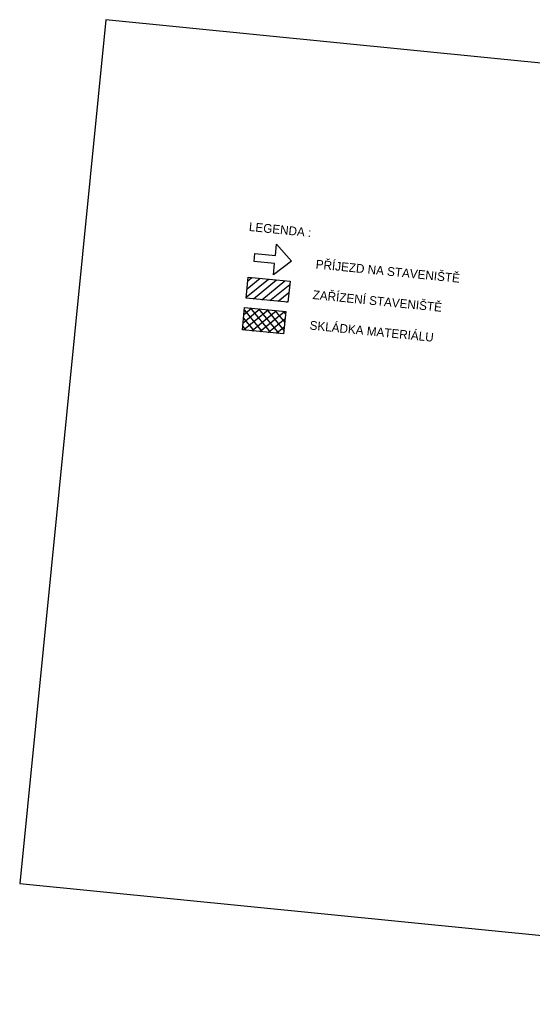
# Model space of a CAD drawing. Extents: x -517955 to -517507, y -1177194 to -1176857.
# Drawn here: x -517954.8 to -517779.6, y -1177194.3 to -1176857.1 of the extents above; entities that cross this region are included whole.
import ezdxf

# ---------------------------------------------------------------- set-up
doc = ezdxf.new("R2010")
doc.units = 0
doc.layers.add('označení lomového bodu', color=7, linetype='Continuous')

msp = doc.modelspace()

# ---------------------------------------------------------------- linework, layer by layer
at = {"layer": 'označení lomového bodu'}
for p, q in [((-517877.37, -1176952.06), (-517869.82, -1176945.88)), ((-517877.09, -1176949.25), (-517872.64, -1176945.6)), ((-517876.81, -1176946.43), (-517875.45, -1176945.32)), ((-517874.9, -1176952.63), (-517867.01, -1176946.16)), ((-517872.09, -1176952.91), (-517864.2, -1176946.44)), ((-517869.27, -1176953.19), (-517862.52, -1176947.66)), ((-517866.46, -1176953.47), (-517862.8, -1176950.47)), ((-517878.46, -1176960.79), (-517872.71, -1176956.08)), ((-517878.18, -1176957.97), (-517875.53, -1176955.8)), ((-517876.02, -1176955.75), (-517869.1, -1176964.19)), ((-517873.2, -1176956.03), (-517866.29, -1176964.47)), ((-517870.39, -1176956.31), (-517864.5, -1176963.5)), ((-517863.64, -1176953.75), (-517863.08, -1176953.29)), ((-517878.34, -1176963.27), (-517869.9, -1176956.36)), ((-517878.31, -1176959.26), (-517874.73, -1176963.63)), ((-517878.03, -1176956.45), (-517871.92, -1176963.91)), ((-517875.52, -1176963.55), (-517867.08, -1176956.64)), ((-517872.71, -1176963.83), (-517864.27, -1176956.92)), ((-517869.89, -1176964.11), (-517864.09, -1176959.36)), ((-517867.57, -1176956.59), (-517864.22, -1176960.68)), ((-517864.76, -1176956.87), (-517863.94, -1176957.87)), ((-517878.59, -1176962.08), (-517877.55, -1176963.35)), ((-517867.08, -1176964.39), (-517864.37, -1176962.18))]:
    msp.add_line(p, q, dxfattribs=at)
for points in [[(-517954.84, -1177152.67), (-517536.91, -1177194.29), (-517507.48, -1176898.75), (-517925.41, -1176857.13)], [(-517874.67, -1176939.8), (-517874.4, -1176937.1), (-517867.41, -1176937.8), (-517867.01, -1176933.88), (-517861.95, -1176939.7), (-517868.06, -1176944.41), (-517867.67, -1176940.49)], [(-517876.69, -1176945.2), (-517862.42, -1176946.62), (-517863.13, -1176953.8), (-517877.4, -1176952.38)], [(-517877.94, -1176955.56), (-517863.85, -1176956.96), (-517864.62, -1176964.64), (-517878.7, -1176963.24)]]:
    msp.add_lwpolyline(points, close=True, dxfattribs=at)

# ---------------------------------------------------------------- texts
for s, p in [('LEGENDA :', (-517876.58, -1176929.38)), ('PŘÍJEZD NA STAVENIŠTĚ', (-517853.74, -1176942.21)), ('ZAŘÍZENÍ STAVENIŠTĚ', (-517854.78, -1176952.66)), ('SKLÁDKA MATERIÁLU', (-517855.82, -1176963.1))]:
    msp.add_text(s, height=3, rotation=354.3133, dxfattribs=at).set_placement(p)

doc.saveas('drawing.dxf')
